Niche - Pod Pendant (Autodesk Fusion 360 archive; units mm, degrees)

design "Pod" references "Luxe Single Pendant Cordset - 4ft Standard", "Pod", "Niche - Chief Architect - Luxe Single Pendant Cordset"
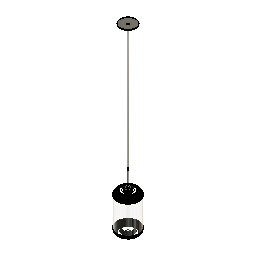
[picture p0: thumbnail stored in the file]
external_derived "ExternalDerived1" bodies "Pod"
external_derived "ExternalDerived2" bodies "Socket Body", "Shade Ring", "Shade Ring +Collar", "Socket", "Body1", "Metal Strain Relief", "Fabric Cord (1)", "Stem (Threaded)"
move "Move1"
external_derived "ExternalDerived3" bodies "T8-Bulb"
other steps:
derived_base_feature "Derived Base Feature1" bodies "Body8", "Pod"
derived_base_feature "Derived Base Feature2" bodies "Socket Body", "Shade Ring", "Shade Ring +Collar", "Socket", "Body1", "Metal Strain Relief", "Fabric Cord (1)", "Stem (Threaded)"
derived_base_feature "Derived Base Feature3" bodies "T8-Bulb"
named bodies: "Body8", "Pod", "Socket Body", "Shade Ring", "Shade Ring +Collar", "Socket", "Body1", "Metal Strain Relief", "Fabric Cord (1)", "Stem (Threaded)", "Cap (Threaded)", "T8-Bulb"

design "Luxe Single Pendant Cordset - 4ft Standard" references "Luxe Canopy - Single Pendant Cordset"
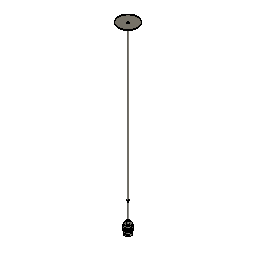
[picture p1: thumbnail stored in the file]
external_derived "ExternalDerived2" bodies "Cap (Threaded)"
move "Move1"
move "Move2"
offset_faces "OffsetFaces1" distance 1051.56
move "Move3"
move "Move4"
move "Move5"
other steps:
derived_base_feature "Derived Base Feature9" bodies "Socket Body", "Shade Ring", "Shade Ring +Collar", "Socket"
derived_base_feature "Derived Base Feature10" bodies "Body1"
derived_base_feature "Derived Base Feature12" bodies "Metal Strain Relief"
derived_base_feature "Derived Base Feature13" bodies "Fabric Cord (1)"
derived_base_feature "Derived Base Feature14" bodies "Stem (Threaded)"
derived_base_feature "Derived Base Feature15" bodies "Cap 9Threaded)", "Cap (Threaded)"
named bodies: "Socket Body", "Shade Ring", "Shade Ring +Collar", "Socket", "Metal Strain Relief", "Fabric Cord (1)", "Stem (Threaded)", "Cap 9Threaded)", "Body1", "Cap (Threaded)", "5M Set Screw"

design "Luxe Canopy - Single Pendant Cordset" references "M5 Set Screw", "Plastic Strain Relief", "Canopy Mounting Bar", "Canopy Mounting Bar Screw", "Luxe Cordset"
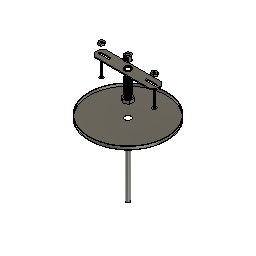
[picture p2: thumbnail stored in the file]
sketch "Sketch1" plane through (0, 0, 0) normal (0, 0, 1) x axis (1, 0, 0)
  circle C1 centre (0, 0) radius 63.5
  point P1 (0, 0)
  point P2 (0, 0)
  coincident P1 P2
  dimension "d1" diameter C1 = 127
extrude "Extrude1" new body sketch "Sketch1" along normal blind 5.08
shell "Shell1" innerThickness 0.762
hole "Hole1" HoleDepth 35.56 HoleDiameter 10.16 TipAngle 118
component_from_bodies "Body->Comp1"
component_insert "Component Insert1"
component_insert "Component Insert2"
component_insert "Component Insert3"
sketch "Sketch2" plane through (0, 0, 0) normal (0, 0, 1) x axis (1, 0, 0)
  circle C1 centre (0, 0) radius 3.175
  point P1 (0, 0)
  point P2 (0, 0)
  coincident P1 P2
  dimension "d8" diameter C1 = 6.35
extrude "Extrude2" new body sketch "Sketch2" along normal blind 127 and against normal blind 127 bodies "Fabric Cord"
component_insert "Component Insert4"
component_insert "Component Insert5"
position "Position1"
sketch "Sketch3" plane through (0, 0, 0.762) normal (0, 0, 1) x axis (-1, 0, 0)
  circle C1 centre (-0.0475, 0.2257) radius 5.08
  circle C2 centre (0, 0) radius 62.738
  circle C3 centre (0, 0) radius 4.826
  concentric C2 C3
  dimension "d13" diameter C3 = 9.652
extrude "Extrude3" new body sketch "Sketch3" profile of C3 along normal blind 25.4 bodies "Threaded Nipple"
shell "Shell2" innerThickness 1.27
thread "Thread1"
sketch "Sketch5" plane through (0, 0, 127) normal (0, 0, 1) x axis (-1, 0, 0)
  line L1 (-6.8191, 3.937) -> (0, 7.874)
  line L2 (-6.8191, -3.937) -> (-6.8191, 3.937)
  line L3 (0, -7.874) -> (-6.8191, -3.937)
  line L4 (6.8191, -3.937) -> (0, -7.874)
  line L5 (6.8191, 3.937) -> (6.8191, -3.937)
  line L6 (0, 7.874) -> (6.8191, 3.937)
  circle C1 centre (0, 0) radius 3.175
  point P2 (0, 0)
  point P9 (0, 0)
  point P3 (0, 7.874)
  coincident P2 P9
  dimension "d20" distance P3 P9 = 7.874
extrude "Extrude4" new body sketch "Sketch5" along normal blind 5.08 bodies "Hex Nut"
move "Move1"
thread "Thread2"
move "Move2" TranslateX 0 TranslateY 0 TranslateZ -55.88
move "Move3" TranslateX 0 TranslateY 0 TranslateZ 60.96
position "Position2"
sketch "Sketch6" plane through (0, 0, 0) normal (0, 0, 1) x axis (1, 0, 0)
  circle C1 centre (0, 0) radius 9.525
  point P1 (0, 0)
  point P2 (0, 0)
  coincident P1 P2
  dimension "d29" diameter C1 = 19.05
extrude "Extrude5" new body sketch "Sketch6" along normal blind 16.129 bodies "Metal Strain Relief"
move "Move4" TranslateX 0 TranslateY 0 TranslateZ -86.36
hole "Hole2" HoleDepth 10.16 HoleDiameter 5.08 TipAngle 118
hole "Hole3" HoleDepth 4.064 HoleDiameter 7.62 TipAngle 180
hole "Hole4" HoleDepth 12.192 HoleDiameter 9.144 TipAngle 180
thread "Thread3" ThreadOffset 0 ThreadLength 6.096
move "Move1" TranslateX 0 TranslateY 0 TranslateZ 68.58
move "Move5" TranslateX 0 TranslateY 0 TranslateZ 138.43
component_insert "Component Insert6"
external_derived "ExternalDerived1" bodies "5M Set Screw"
move "Move6" TranslateX 0 TranslateY 0 TranslateZ -185.42
copy_paste_bodies "CopyPasteBodies1"
move "Move7" TranslateX 0 TranslateY 0 TranslateZ -12.7
offset_faces "OffsetFaces1" distance -152.4
move "Move8"
component_from_bodies "Body->Comp2"
component_from_bodies "Body->Comp3"
component_from_bodies "Body->Comp4"
component_from_bodies "Body->Comp5"
hole "Hole1" HoleDepth 25.4 HoleDiameter 6.35 TipAngle 180
sketch "Sketch7" plane through (0, 0, 0) normal (0, 0, 1) x axis (1, 0, 0)
  line L1 (49.784, 3.9595) -> (52.07, 0)
  line L2 (45.212, 3.9595) -> (49.784, 3.9595)
  line L3 (42.926, 0) -> (45.212, 3.9595)
  line L4 (45.212, -3.9595) -> (42.926, 0)
  line L5 (49.784, -3.9595) -> (45.212, -3.9595)
  line L6 (52.07, 0) -> (49.784, -3.9595)
  point P2 (52.07, 0)
  point P8 (47.498, 0)
  dimension "d63" distance P2 P8 = 4.572
extrude "Extrude6" new body sketch "Sketch7" along normal blind 3.175 bodies "Mounting Hex Nut"
hole "Hole5" HoleDepth 25.4 HoleDiameter 3.81 TipAngle 180
thread "Thread4"
move "Move9"
component_from_bodies "Body->Comp6"
copy_paste "CopyPaste1"
move "Move10"
derived_base_feature "Derived Base Feature3" bodies "Stem (Threaded)", "Cap 9Threaded)"
move "Move11"
component_from_bodies "Body->Comp7"
component_from_bodies "Body->Comp8"
component_from_bodies "Body->Comp9"
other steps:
base_feature "Base Feature1"
base_feature "Base Feature1" bodies "Stem (Threaded)"
base_feature "Base Feature1" bodies "Cap 9Threaded)"
base_feature "Base Feature1" bodies "Fabric Cord"
base_feature "Base Feature1" bodies "Metal Strain Relief"
base_feature "Base Feature1" bodies "Mounting Hex Nut"
base_feature "Base Feature1" bodies "Hex Nut"
base_feature "Base Feature1" bodies "Fabric Cord (1)"
base_feature "Base Feature1" bodies "Threaded Nipple"
derived_base_feature "Derived Base Feature1" bodies "Socket Body", "Shade Ring", "Shade Ring +Collar", "Socket", "Rigid Stem"
derived_base_feature "Derived Base Feature2" bodies "5M Set Screw"
base_feature "Base Feature1" bodies "Fabric Cord", "Fabric Cord (1)"
create_component "CreateComponent1"
remove_body "RemoveBody1"
create_component "CreateComponent2"
remove_body "RemoveBody2"
create_component "CreateComponent3"
remove_body "RemoveBody3"
create_component "CreateComponent4"
remove_body "RemoveBody4"
create_component "CreateComponent5"
remove_body "RemoveBody5"
create_component "CreateComponent6"
remove_body "RemoveBody6"
create_component "CreateComponent7"
remove_body "RemoveBody7"
create_component "CreateComponent8"
remove_body "RemoveBody8"
create_component "CreateComponent9"
remove_body "RemoveBody9"
named bodies: "Fabric Cord", "Threaded Nipple", "Hex Nut", "Metal Strain Relief", "Socket Body", "Shade Ring", "Shade Ring +Collar", "Socket", "Rigid Stem", "5M Set Screw", "Fabric Cord (1)", "Mounting Hex Nut", "Stem (Threaded)", "Cap 9Threaded)"

design "Niche - Chief Architect - Luxe Single Pendant Cordset"
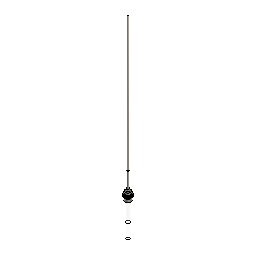
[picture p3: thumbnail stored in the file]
derived_base_feature "Derived Base Feature" bodies "Socket Body", "Shade Ring", "Shade Ring +Collar", "Socket", "Canopy", "Metal Strain Relief", "Fabric Cord (1)", "Stem (Threaded)"
remove_body "RemoveBody1"
remove_body "RemoveBody2"
split "Split1" bodies "Socket Body (1)"
remove_body "RemoveBody3"
align "Align1"
hole "Hole1" HoleDepth 19.05 HoleDiameter 8.89 TipAngle 118
combine "Combine1" bodies "Shade Ring"
split "Split2" bodies "Socket (1)"
remove_body "RemoveBody4"
split "Split3" bodies "Fabric Cord (1) (1)"
remove_body "RemoveBody5"
combine "Combine2" bodies "Socket Body"
align "Align2"
combine "Combine3" bodies "Metal Strain Relief"
sketch "Sketch1" plane through (0, 0, 0) normal (0, 1, 0) x axis (1, 0, 0)
  line L1 (13.1098, 24.9049) -> (-12.2902, 24.9049)
  line L2 (18.1898, 37.1766) -> (18.1898, 29.9849)
  line L3 (-17.3702, 29.9849) -> (-17.3702, 36.7132)
  line L4 (0, 132.969) -> (0, 24.9049)
  arc A1 centre (0, 86.36) radius 46.609 clockwise from (-22.6031, 45.5985) to (23.276, 45.979)
  arc A2 centre (-27.5302, 36.7132) radius 10.16 clockwise from (-22.6031, 45.5985) to (-17.3702, 36.7132)
  arc A3 centre (28.3498, 37.1766) radius 10.16 clockwise from (18.1898, 37.1766) to (23.276, 45.979)
  arc A4 centre (-12.2902, 29.9849) radius 5.08 clockwise from (-12.2902, 24.9049) to (-17.3702, 29.9849)
  arc A5 centre (13.1098, 29.9849) radius 5.08 clockwise from (18.1898, 29.9849) to (13.1098, 24.9049)
  point P5 (18.1898, 43.4469)
  point P3 (-17.3702, 24.9049)
  point P4 (18.1898, 24.9049)
  point P18 (0, 24.9049)
  point P19 (0, 132.969)
  horizontal L1
  vertical L2
  vertical L3
  tangent A1 A2
  tangent L3 A2
  coincident P5 L2
  coincident P5 A1
  tangent L2 A3
  tangent A1 A3
  equal A2 A3
  coincident P3 L1
  coincident P3 L3
  tangent L1 A4
  tangent L3 A4
  coincident P4 L1
  coincident P4 L2
  tangent L1 A5
  tangent L2 A5
  coincident L1 P18
  coincident A1 P19
  perpendicular L1 L4
  dimension "d4" diameter A1 = 93.218
  dimension "d5" distance P3 P4 = 35.56
  dimension "d6" distance P4 P5 = 18.542
  dimension "d7" radius A2 = 10.16
  dimension "d8" radius A4 = 5.08
  dimension "d9" radius A5 = 5.08
revolve "Revolve1" sketch "Sketch1" AlongAngle 360 bodies "G30-Bulb"
move "Move1"
sketch "Sketch2" plane through (0, 0, 0) normal (0, 1, 0) x axis (1, 0, 0)
  line L1 (12.7, 0) -> (-12.7, 0)
  line L2 (12.7, 152.4) -> (12.7, 0)
  line L3 (-12.7, 0) -> (-12.7, 152.4)
  line L4 (0, 165.1) -> (0, 0)
  arc A1 centre (0, 152.4) radius 12.7 clockwise from (-12.7, 152.4) to (12.7, 152.4)
  point P1 (0, 0)
  point P7 (0, 0)
  point P8 (0, 165.1)
  horizontal L1
  vertical L2
  vertical L3
  coincident P1 P7
  midpoint A1 P8
  perpendicular L1 L4
revolve "Revolve2" sketch "Sketch2" AlongAngle 360 bodies "T9-Bulb"
move "Move2"
sketch "Sketch3" plane through (0, 0, 0) normal (0, 1, 0) x axis (1, 0, 0)
  line L1 (12.7, 0) -> (-12.7, 0)
  line L2 (12.7, 254) -> (12.7, 0)
  line L3 (-12.7, 0) -> (-12.7, 254)
  line L4 (0, 266.7) -> (0, 0)
  arc A1 centre (0, 254) radius 12.7 clockwise from (-12.7, 254) to (12.7, 254)
  point P1 (0, 0)
  point P7 (0, 0)
  point P8 (0, 266.7)
  horizontal L1
  vertical L2
  vertical L3
  coincident P1 P7
  midpoint A1 P8
  perpendicular L1 L4
revolve "Revolve3" sketch "Sketch3" AlongAngle 360 bodies "T8-Bulb"
move "Move3"
move "Move4"
move "Move5"
sketch "Sketch4" plane through (0, 0, 0) normal (0, 1, 0) x axis (1, 0, 0)
  line L1 (15.875, -8.763) -> (-15.875, -8.763)
  line L2 (15.875, 22.987) -> (15.875, -8.763)
  line L3 (-15.875, 22.987) -> (15.875, 22.987)
  line L4 (-15.875, -8.763) -> (-15.875, 22.987)
  line L5 (0, 22.987) -> (0, -8.763)
  point P6 (0, -8.763)
  point P7 (0, 22.987)
  point P2 (-15.875, -8.763)
  point P3 (15.875, -8.763)
  point P5 (-15.875, 22.987)
  horizontal L1
  vertical L2
  horizontal L3
  vertical L4
  midpoint L1 P6
  midpoint L3 P7
  dimension "d13" distance P2 P3 = 31.75
  dimension "d14" distance P2 P5 = 31.75
revolve "Revolve4" sketch "Sketch4" AlongAngle 360 bodies "Bulb Extender"
move "Move6"
sketch "Sketch5" plane through (0, 0, 0) normal (0, 1, 0) x axis (1, 0, 0)
  line L1 (-12.7, 35.56) -> (12.7, 35.56)
  line L2 (-12.7, 5.08) -> (-12.7, 35.56)
  line L3 (12.7, 5.08) -> (-12.7, 5.08)
  line L4 (12.7, 35.56) -> (12.7, 5.08)
  line L5 (-12.7, 5.08) -> (12.7, 35.56)
  line L6 (12.7, 5.08) -> (-12.7, 35.56)
  line L7 (0, 35.56) -> (0, 5.08)
  point P6 (0, 20.32)
  point P7 (0, 5.08)
  point P8 (0, 35.56)
  horizontal L1
  perpendicular L1 L2
  parallel L1 L3
  parallel L2 L4
  coincident L5 P6
  coincident L6 P6
  midpoint L3 P7
  midpoint L1 P8
revolve "Revolve5" sketch "Sketch5" AlongAngle 360 bodies "Y-Spliter"
sketch "Sketch6" plane through (0, 0, 0) normal (0, 1, 0) x axis (1, 0, 0)
  line L1 (-55.88, 64.9514) -> (-21.59, 64.9514)
  line L2 (-55.88, 35.7414) -> (-55.88, 64.9514)
  line L3 (-21.59, 35.7414) -> (-55.88, 35.7414)
  line L4 (-21.59, 64.9514) -> (-21.59, 35.7414)
  line L5 (-55.88, 35.7414) -> (-21.59, 64.9514)
  line L6 (-21.59, 35.7414) -> (-55.88, 64.9514)
  line L7 (-38.735, 64.9514) -> (-38.735, 35.7414)
  point P6 (-38.735, 50.3464)
  point P7 (-38.735, 35.7414)
  point P8 (-38.735, 64.9514)
  point P4 (-55.88, 35.7414)
  point P5 (-21.59, 35.7414)
  point P2 (-21.59, 64.9514)
  horizontal L1
  perpendicular L1 L2
  parallel L1 L3
  parallel L2 L4
  coincident L5 P6
  coincident L6 P6
  midpoint L3 P7
  midpoint L1 P8
  dimension "d17" distance P4 P5 = 34.29
  dimension "d18" distance P2 P5 = 29.21
revolve "Revolve6" sketch "Sketch6" AlongAngle 360
chamfer "Chamfer1" distance 7.62
move "Move7"
mirror "Mirror1" mirrorStitchTolerance 0.1016
move "Move8"
combine "Combine4"
move "Move9"
sketch "Sketch7" plane through (0, 0, 0) normal (0, 1, 0) x axis (1, 0, 0)
  line L1 (-15.24, 40.64) -> (-15.24, 48.1816)
  line L2 (12.7, 38.1) -> (-12.7, 38.1)
  line L3 (15.24, 48.1816) -> (15.24, 40.64)
  line L4 (0, 100.1623) -> (0, 38.1)
  arc A1 centre (0, 76.2) radius 23.9623 clockwise from (-19.7282, 62.5988) to (19.7282, 62.5988)
  arc A2 centre (-40.64, 48.1816) radius 25.4 clockwise from (-19.7282, 62.5988) to (-15.24, 48.1816)
  arc A3 centre (40.64, 48.1816) radius 25.4 clockwise from (15.24, 48.1816) to (19.7282, 62.5988)
  arc A4 centre (-12.7, 40.64) radius 2.54 clockwise from (-12.7, 38.1) to (-15.24, 40.64)
  arc A5 centre (12.7, 40.64) radius 2.54 clockwise from (15.24, 40.64) to (12.7, 38.1)
  point P15 (0, 38.1)
  point P16 (0, 100.1623)
  parallel L1 L3
  tangent A1 A2
  tangent L1 A2
  tangent A1 A3
  tangent L3 A3
  tangent L1 A4
  tangent L2 A4
  tangent L2 A5
  tangent L3 A5
  midpoint L2 P15
  midpoint A1 P16
  perpendicular L2 L4
  dimension "d23" radius A2 = 25.4
  dimension "d24" radius A3 = 25.4
  dimension "d25" radius A4 = 2.54
  dimension "d26" radius A5 = 2.54
revolve "Revolve7" sketch "Sketch7" AlongAngle 360 bodies "A15-Bulb"
move "Move10"
copy_paste_bodies "CopyPasteBodies1"
copy_paste_bodies "CopyPasteBodies2"
move "Move11"
mirror "Mirror2" mirrorStitchTolerance 0.1016 bodies "A15-Bulb (1) (1)"
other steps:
base_feature "Base Feature1" bodies "Y-Spliter", "Bulb Extender", "Y-Spliter (1)", "Bulb Extender (1)"
base_feature "Base Feature2" bodies "A15-Bulb", "A15-Bulb (1)"
named bodies: "Socket Body", "Shade Ring", "Shade Ring +Collar", "Socket", "Canopy", "Metal Strain Relief", "Fabric Cord (1)", "Stem (Threaded)", "Adapter", "5M Set Screw", "Body1 (1)", "Socket Body (1)", "Socket (1)", "Fabric Cord (1) (1)", "G30-Bulb", "T9-Bulb", "T8-Bulb", "Bulb Extender", "Y-Spliter", "A15-Bulb", "Y-Spliter (1)", "Bulb Extender (1)", "A15-Bulb (1)", "A15-Bulb (1) (1)"

design "M5 Set Screw"
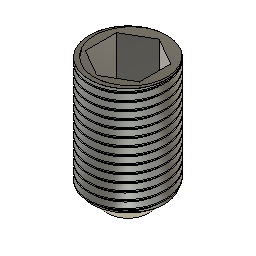
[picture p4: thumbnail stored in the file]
sketch "Sketch1" plane through (0, 0, 0) normal (0, 0, 1) x axis (1, 0, 0)
  circle C1 centre (0, 0) radius 2.5
  point P1 (0, 0)
  point P2 (0, 0)
  coincident P1 P2
  dimension "d1" diameter C1 = 5
extrude "Extrude1" new body sketch "Sketch1" along normal blind 8
sketch "Sketch2" plane through (0, 0, 8) normal (0, 0, 1) x axis (-1, 0, 0)
  line L1 (-1.7321, 1) -> (0, 2)
  line L2 (-1.7321, -1) -> (-1.7321, 1)
  line L3 (0, -2) -> (-1.7321, -1)
  line L4 (1.7321, -1) -> (0, -2)
  line L5 (1.7321, 1) -> (1.7321, -1)
  line L6 (0, 2) -> (1.7321, 1)
  circle C1 centre (0, 0) radius 2.5
  point P2 (0, 0)
  point P9 (0, 0)
  coincident P2 P9
extrude "Extrude2" cut sketch "Sketch2" profile of L1 L2 L3 L4 L5 L6 against normal blind 3
thread "Thread1" ThreadOffset 0.99 ThreadLength 7
chamfer "Chamfer1" distance 1.15

design "Luxe Cordset" references "M5 Set Screw"
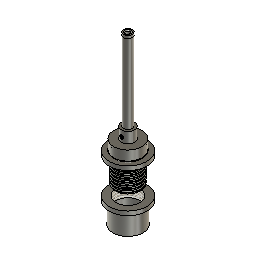
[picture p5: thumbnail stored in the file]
sketch "Sketch1" plane through (0, 0, 0) normal (0, 0, 1) x axis (1, 0, 0)
  circle C1 centre (0, 0) radius 20.6
  point P1 (0, 0)
  point P2 (0, 0)
  coincident P1 P2
  dimension "d11" diameter C1 = 41.2
extrude "Extrude1" new body sketch "Sketch1" along normal blind 14 bodies "Socket Body"
sketch "Sketch2" plane through (0, 0, 14) normal (0, 0, 1) x axis (-1, 0, 0)
  circle C1 centre (0, 0) radius 20.6
  circle C2 centre (0, 0) radius 9.6
  concentric C1 C2
  dimension "d3" diameter C2 = 19.2
extrude "Extrude2" add sketch "Sketch2" profile of C2 along normal blind 15.75
sketch "Sketch3" plane through (0, 0, 29.75) normal (0, 0, 1) x axis (-1, 0, 0)
  circle C1 centre (0, 0) radius 9.6
  circle C2 centre (0, 0) radius 5.75
  concentric C1 C2
  dimension "d6" diameter C2 = 11.5
extrude "Extrude3" new body sketch "Sketch3" profile of C2 along normal blind 114 bodies "Rigid Stem"
move "Move1"
sketch "Sketch4" plane through (0, 0, 203.75) normal (0, 0, 1) x axis (-1, 0, 0)
  circle C1 centre (0, 0) radius 5.75
  circle C2 centre (0, 0) radius 27.5
  dimension "d10" diameter C2 = 55
extrude "Extrude4" new body sketch "Sketch4" profile of C2 along normal blind 6 bodies "Shade Ring"
hole "Hole1" HoleDepth 25 HoleDiameter 42.75 TipAngle 118
sketch "Sketch5" plane through (0, 0, 0) normal (0, 0, 1) x axis (1, 0, 0)
  circle C1 centre (0, 0) radius 22
  point P1 (0, 0)
  point P2 (0, 0)
  coincident P1 P2
  dimension "d18" diameter C1 = 44
move "Move2"
copy_paste_bodies "CopyPasteBodies1"
move "Move3"
sketch "Sketch6" plane through (0, 0, 60) normal (0, 0, -1) x axis (1, 0, 0)
  circle C1 centre (0, 0) radius 20.6
  circle C2 centre (0, 0) radius 21.375
  circle C3 centre (0, 0) radius 20
  concentric C1 C2
  concentric C1 C3
  dimension "d21" diameter C2 = 42.75
  dimension "d24" diameter C3 = 40
cylinder_primitive "CylinderPrimitive1" Height 8 Diameter 42.75
thread "Thread1"
thread "Thread3"
hole "Hole2" HoleDepth 18 HoleDiameter 39 TipAngle 180
move "Move4"
move "Move5"
move "Move6"
hole "Hole3" HoleDepth 114 HoleDiameter 7.6 TipAngle 180
derived_base_feature "Derived Base Feature" bodies "Socket"
move "Move7"
scale "Scale1" ScaleX 1.2 ScaleY 1.2
move "Move8"
sketch "Sketch8" plane through (0, 0, -23.9827) normal (0, 0, -1) x axis (1, 0, 0)
  circle C1 centre (0, -0.036) radius 27.5
  circle C2 centre (0, -0.036) radius 22
  circle C3 centre (0, -0.036) radius 19.5
  dimension "d36" diameter C2 = 44
  dimension "d42" = -2.5
extrude "Extrude7" add sketch "Sketch8" profile of C2 C3 along normal blind 30
offset_faces "OffsetFaces1" distance 2.75
offset_faces "OffsetFaces2" distance -9
thread "Thread2"
move "Move9"
move "Move10"
move "Move11"
scale "Scale2" ScaleZ 1.2
move "Move12"
move "Move13"
move "Move14"
move "Move15"
move "Move16"
split_face "SplitFace1"
move "Move17"
move "Move18"
move "Move19"
move "Move20"
move "Move21"
move "Move22"
move "Move23"
move "Move24"
move "Move25"
move "Move26"
move "Move27"
thread "Thread4"
move "Move28"
move "Move29"
move "Move30"
hole "Hole4" HoleDepth 21 HoleDiameter 39.35 TipAngle 180
hole "Hole5" HoleDepth 9 HoleDiameter 5 TipAngle 180
move "Move31"
move "Move32"
hole "Hole6" HoleDepth 20 HoleDiameter 10 TipAngle 180
move_face "MoveFace3"
move "Move33"
move "Move34"
move "Move35"
move "Move36"
move "Move37"
thread "Thread5" ThreadOffset 0 ThreadLength 6
thread "Thread6" ThreadOffset 0 ThreadLength 6
move "Move38"
move "Move39"
move "Move40"
move "Move41"
component_insert "Component Insert"
thread "Thread7" ThreadOffset 0.5 ThreadLength 5.337
chamfer "Chamfer1" distance 0.5 distance 0.35
sketch "Sketch12" plane through (0, 0, 0) normal (0, 0, 1) x axis (1, 0, 0)
  circle C1 centre (0, 0) radius 6.35
  dimension "d60" diameter C1 = 12.7
extrude "Extrude8" new body sketch "Sketch12" along normal blind 115 bodies "Stem (Threaded)"
hole "Hole7" HoleDepth 115 HoleDiameter 9.65 TipAngle 118
thread "Thread8" ThreadOffset 0 ThreadLength 12.5
thread "Thread9" ThreadOffset 0 ThreadLength 12.5
sketch "Sketch13" plane through (0, 0, 0) normal (0, 0, 1) x axis (1, 0, 0)
  circle C1 centre (0, 0) radius 6.35
  point P1 (0, 0)
  point P2 (0, 0)
  coincident P1 P2
  dimension "d70" diameter C1 = 12.7
extrude "Extrude9" new body sketch "Sketch13" along normal blind 4 bodies "Cap 9Threaded)"
sketch "Sketch14" plane through (0, 0, 4) normal (0, 0, 1) x axis (-1, 0, 0)
  circle C1 centre (0, 0) radius 6.35
  circle C2 centre (0, 0) radius 4.5
  concentric C1 C2
  dimension "d73" diameter C2 = 9
extrude "Extrude10" add sketch "Sketch14" profile of C2 against normal blind 14
thread "Thread10"
hole "Hole8" HoleDepth 115 HoleDiameter 6.5 TipAngle 118 CSDiameter 9 CSAngle 90
move "Move42"
move "Move43"
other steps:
base_feature "Base Feature" bodies "Shade Ring +Collar"
named bodies: "Socket Body", "Shade Ring", "Shade Ring +Collar", "Socket", "Rigid Stem", "Stem (Threaded)", "Cap 9Threaded)"

design "Niche_Pod_Single_Pendant"
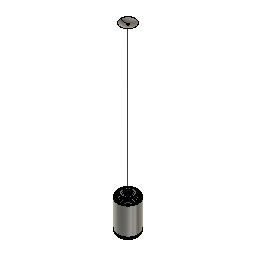
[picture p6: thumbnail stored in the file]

design "Pod" references "Niche_Pod_Single_Pendant"
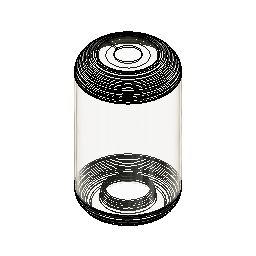
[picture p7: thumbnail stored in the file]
external_derived "ExternalDerived" bodies "Pod"
fillet "Fillet1" radius 25.4
fillet "Fillet2" radius 25.4
fillet "Fillet3" radius 17.78
fillet "Fillet4" radius 25.4
fillet "Fillet5" radius 22.86
fillet "Fillet6" radius 15.24
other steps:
derived_base_feature "Derived Base Feature" bodies "Pod"
named bodies: "Pod"

design "Plastic Strain Relief"
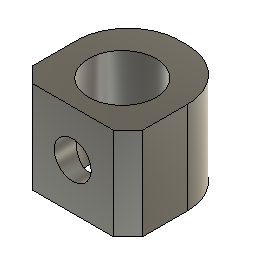
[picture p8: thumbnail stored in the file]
base_feature "Base Feature" bodies "strainrelief"
named bodies: "strainrelief"

design "Canopy Mounting Bar Screw"
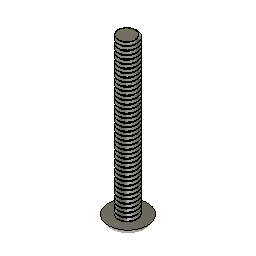
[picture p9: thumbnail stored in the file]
base_feature "Base Feature" bodies "screw1"
named bodies: "screw1"

design "Canopy Mounting Bar"
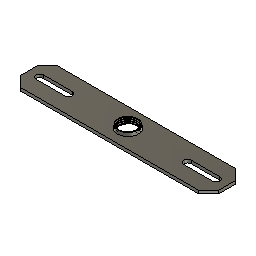
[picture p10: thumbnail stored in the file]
base_feature "Base Feature" bodies "mountingbar"
named bodies: "mountingbar"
